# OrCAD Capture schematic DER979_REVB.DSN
size D
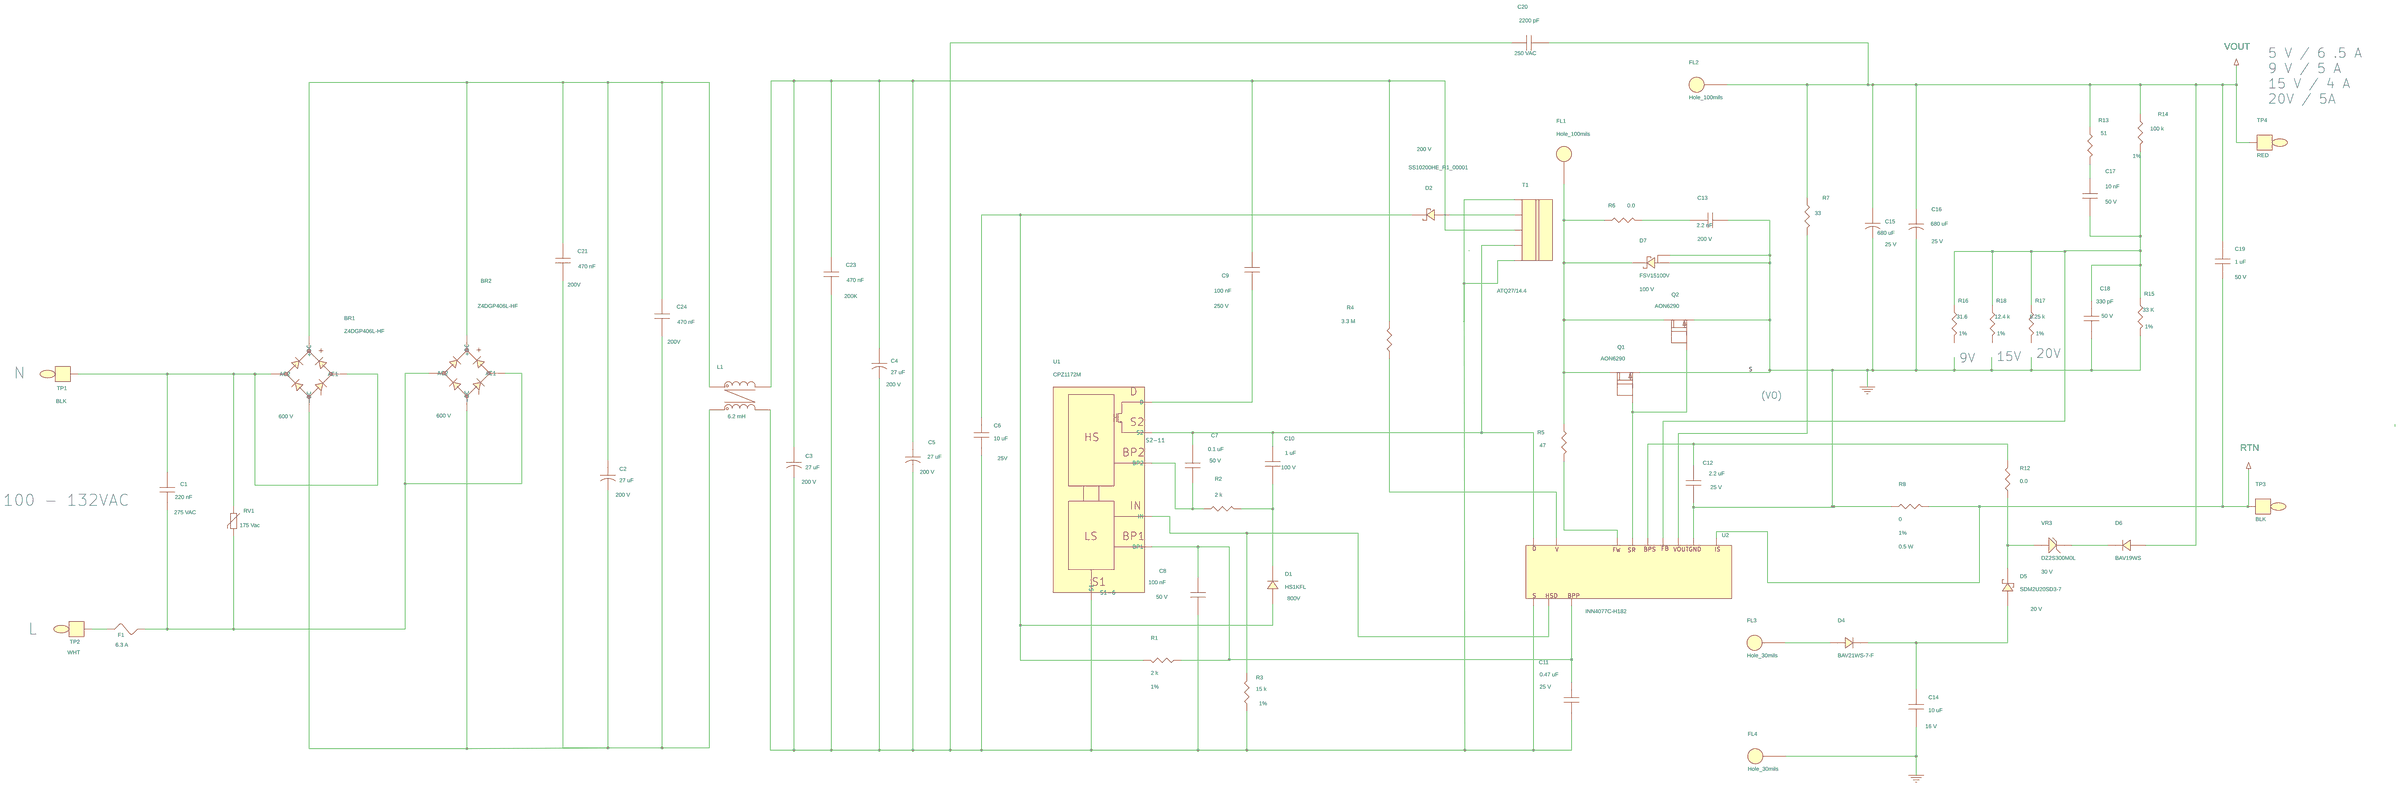
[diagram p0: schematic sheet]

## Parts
BR1  Z4DGP406L-HF  [pi_sm_d_z4d]
BR2  Z4DGP406L-HF  [pi_sm_d_z4d]
C1  220 nF  [pinpxcaprad475x255500040]
C2  27 uF  [pipolcapcyld400ls200040]
C3  27 uF  [pipolcapcyld400ls200040]
C4  27 uF  [pipolcapcyld400ls200040]
C5  27 uF  [pipolcapcyld400ls200040]
C6  10 uF  [pismc0805]
C7  0.1 uF  [pismc0603]
C8  100 nF  [pismc0603]
C9  100 nF  [pismc1206]
C10  1 uF  [pismc0805]
C11  0.47 uF  [pismc0805]
C12  2.2 uF  [pismc0805]
C13  2.2 nF  [pismc0805]
C14  10 uF  [pismc0805]
C15  680 uF  [pipolcapcyld8mmd030]
C16  680 uF  [pipolcapcyld8mmd030]
C17  10 nF  [pismr0402]
C18  330 pF  [pismc0603]
C19  1 uF  [pismc0805]
C20  2200 pF  [pinpcapraD9mmxLS10mm030]
C21  470 nF  [pismc1812]
C23  470 nF  [pismc1812]
C24  470 nF  [pismc1812]
D1  HS1KFL  [pi_sm_sod-123_12]
D2  SS10200HE_R1_00001  [pi_sm_sod-123HE]
D4  BAV21WS-7-F  [pismsod323]
D5  SDM2U20SD3-7  [pismsod323]
D6  BAV19WS  [pismsod323]
D7  FSV15100V  [pi_sm_d_to-277a]
F1  6.3 A  [pi_v_ax_3-6x10_145ls200d030]
FL1  Hole_100mils  [pi_hole_100mil]
FL2  Hole_100mils  [pi_hole_100mil]
FL3  Hole_30mils  [pi_hole_30mil]
FL4  Hole_30mils  [pi_hole_30mil]
L1  6.2 mH  [pi_CMC_18mH_Sumida]
Q1  AON6290  [pismpqfn5x6b]
Q2  AON6290  [pismpqfn5x6b]
R1  2 k  [pismr0603]
R2  2 k  [pismr0603]
R3  15 k  [pismr0603]
R4  3.3 M  [pismr1206]
R5  47  [pismr0603]
R6  0.0  [pismr1206]
R7  33  [pismr0603]
R8  0  [pismr0805]
R12  0.0  [pismr0603]
R13  51  [pismr0402]
R14  100 k  [pismr0603]
R15  33 K  [pismr0603]
R16  31.6  [pismr0603]
R17  8.25 k  [pismr0603]
R18  12.4 k  [pismr0603]
RV1  175 Vac  [pi_disc_335x240ls200d040]
T1  ATQ27/14.4  [pi_bobbin_ATQ27_V_5P]
TP1  BLK  [pitpkeystone100x100]
TP2  WHT  [pitpkeystone100x100]
TP3  BLK  [pitpkeystone100x100]
TP4  RED  [pitpkeystone100x100]
U1  CPZ1172M  [PI_SM_MinSOP16A_1]
U2  INN4077C-H182  [pi_ic_insop_24d_IPC]
VR3  DZ2S300M0L  [pi_sm_d_ssmini2p]

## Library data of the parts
BR1 BR2 = DISCRETE_BRIDGE_+~~-: Disp_Voltage: 600 V; Part Number: 15-01613-00
C1 = CAP_NP: COMPGROUP: 1; Disp_Voltage: 275 VAC; Part Number: 20-00776-00; Voltage: 275 VAC
C2-C5 = CAP_POL: ALT_SYMBOLS: pipolcapclyd400x675ls200040h; Disp_Voltage: 200 V; FPLIST: pipolcapcyld400ls200040,pipolcapclyd400x675ls200040h; Part Number: 20-00610-00; Voltage: 200 V
C6 = CAP_NP: Disp_Voltage: 25V; Part Number: 20-01673-00; Voltage: 25 V
C7 = CAP_NP: ALT_SYMBOLS: cc0603; Disp_Voltage: 50 V; FPLIST: pismc0603,cc0603; Part Number: 20-01434-00; ROOM: 2; Voltage: 50 V
C8 = CAP_NP: Disp_Voltage: 50 V; Part Number: 20-01693-00; ROOM: 2; Voltage: 50 V
C9 = CAP_NP: Disp_Voltage: 250 V; Part Number: 20-01011-00; ROOM: 1; Voltage: 250 V
C10 = CAP_NP: Disp_Voltage: 100 V; Part Number: 20-01324-00; ROOM: 2; Voltage: 100 V
C11 = CAP_NP: Disp_Voltage: 25 V; Part Number: 20-09182-00; ROOM: 3; Voltage: 25 V
C12 = CAP_NP: Disp_Voltage: 25 V; Part Number: 20-01594-00; ROOM: 3; Voltage: 25 V
C13 = CAP_NP: Disp_Voltage: 200 V; Part Number: 20-00761-00; ROOM: 3; Voltage: 200 V
C14 = CAP_NP: Disp_Voltage: 16 V; Part Number: 20-08964-00; ROOM: 3; Voltage: 16 V
C15 = CAP_POL: ALT_SYMBOLS: pipolcapcyld8x16mmd030H; COMPGROUP: 3; Disp_Voltage: 25 V; FPLIST: pipolcapcyld8mmd030,pipolcapcyld8x16mmd030H; Part Number: 20-01579-00; ROOM: 3; Voltage: 25 V
C16 = CAP_POL: ALT_SYMBOLS: pipolcapcyld8x16mmd030H; Disp_Voltage: 25 V; FPLIST: pipolcapcyld8mmd030,pipolcapcyld8x16mmd030H; Part Number: 20-01579-00; ROOM: 3; Voltage: 25 V
C17 = CAP_NP: Disp_Voltage: 50 V; Part Number: 20-09250-00; ROOM: 3; Voltage: 50 V
C18 = CAP_NP: ALT_SYMBOLS: pismc0603_1; Disp_Voltage: 50 V; FPLIST: pismc0603,pismc0603_1; Part Number: 20-09235-00; ROOM: 3; Voltage: 50 V
C19 = CAP_NP: Disp_Voltage: 50 V; Part Number: 20-00853-00; ROOM: 4; Voltage: 50 V
C20 = CAP_NP: Disp_Voltage: 250 VAC; Part Number: 20-01656-00; Voltage: 250 VAC
C21 C24 = CAP_NP: Disp_Voltage: 200V; Part Number: 20-08693-00; Voltage: 200V
C23 = CAP_NP: Disp_Voltage: 200K; Part Number: 20-08693-00; Voltage: 200V
D1 = DIODE: COMPGROUP: 2; Disp_Voltage: 800V; Part Number: 15-01686-00; ROOM: 2
D2 = DIODE_SCHOTTKY: Disp_Voltage: 200 V; Part Number: 15-01774-00; ROOM: 1
D4 = DIODE: Part Number: 15-00385-00
D5 = DIODE_SCHOTTKY: Disp_Voltage: 20 V; Part Number: 15-01176-00
D6 = DIODE: Part Number: 15-00658-00
D7 = DIODE_SCHOTTKY_TO-277A: Disp_Voltage: 100 V; Part Number: 15-01838-00
F1 = FUSE: ALT_SYMBOLS: pi_axial_3_6x10_145ls500d030; FPLIST: pi_v_ax_3-6x10_145ls200d030,pi_axial_3_6x10_145ls500d030; Part Number: 40-00028-00
FL1 = FlyingLead: Part Number: 35-00432-00
FL2 = FlyingLead: Part Number: 35-00432-00; ROOM: 3
FL3 FL4 = FlyingLead: Part Number: 35-00284-00; ROOM: 3
L1 = TORRID_4P_12_43a: ALT_SYMBOLS: pi_CMC_18mH_SumidaW,pi_CMC_18mH_Sumida_H,pi_CMC_18mH_SumidaSF; FPLIST: pi_CMC_18mH_Sumida,pi_CMC_18mH_SumidaW,pi_CMC_18mH_Sumida_H,pi_CMC_18mH_SumidaSF; Part Number: 30-00462-00
Q1 Q2 = FET_N_SGD_123_4_5678: Part Number: 50-00328-00; ROOM: 3
R1 = R: Disp_Tol: 1%; Part Number: 05-01107-00; ROOM: 2
R2 = R: ALT_SYMBOLS: pismr0603_1; FPLIST: pismr0603,pismr0603_1; Part Number: 05-01695-00; ROOM: 2
R3 = R: Disp_Tol: 1%; Part Number: 05-03199-00; ROOM: 2
R4 = R: Part Number: 05-01433-00; ROOM: 2
R5 = R: ALT_SYMBOLS: pismr0603_1; FPLIST: pismr0603,pismr0603_1; Part Number: 05-01656-00; ROOM: 4
R6 = R: Part Number: 05-03160-00; ROOM: 3
R7 = R: Part Number: 05-01652-00; ROOM: 3
R8 = R: Disp_Power: 0.5 W; Disp_Tol: 1%; Part Number: 05-06481-00
R12 = R: Part Number: 05-03158-00; ROOM: 3
R13 = R: Part Number: 05-06185-00; ROOM: 3
R14 = R: Disp_Tol: 1%; Part Number: 05-01174-00; ROOM: 3
R15 = R: Disp_Tol: 1%; Part Number: 05-06465-00; ROOM: 3
R16 = R: Disp_Tol: 1%; Part Number: 05-00934-00; ROOM: 3
R17 = R: Disp_Tol: 1%; Part Number: 05-01166-00; ROOM: 3
R18 = R: Disp_Tol: 1%; Part Number: 05-03191-00; ROOM: 3
RV1 = VARISTOR: Part Number: 85-00025-00
T1 = BATQ27_5P_GENERIC: Part Number: 25-01192-00
TP1 TP3 = TESTPOINT: ALT_SYMBOLS: TP_TH_CR2_D1_1; FPLIST: pitpkeystone100x100,TP_TH_CR2_D1_1; Part Number: 35-00079-00
TP2 = TESTPOINT: Part Number: 35-00081-00
TP4 = TESTPOINT: Part Number: 35-00080-00
U1 = ClampZeroMinSOP16: Part Number: 10-01212-00; ROOM: 2
U2 = MinnoPriSecCZ: ALT_SYMBOLS: pi_ic_insop_24d,PI_IC_INSOP24B; FPLIST: pi_ic_insop_24d_IPC, pi_ic_insop_24d,PI_IC_INSOP24B; Part Number: 10-01408-00; ROOM: 3
VR3 = DIODE_ZENER: Disp_Voltage: 30 V; Part Number: 15-00996-00

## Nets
GND: C12.2 C13.1 C14.2 C15.2 C16.2 C18.2 D7.1(A1) D7.2(A2) FL4.1 Q1.1(S) Q2.1(S) R8.2 R15.2 U2.2
RTN: C19.1 R8.1 TP3.1 U2.1
Vout: C15.1 C16.1 C19.2 C20.2 D6.2 FL2.1 R7.1 R13.1 R14.1 TP4.1
N10971121: C8.1 C11.1 R1.2 U1.8(BP1) U2.14
N10972629: C17.2 C18.1 R14.2 R15.1 R16.1 R17.1 R18.1 U2.3
N10986441: R4.2 U2.13
N10993526: C7.2 C10.1 T1.4 U1.10(S2) U2.24
N11033773: C3.2 C4.2 C5.2 C6.2 C8.2 C11.2 C20.1 C23.2 L1.2 R3.1 T1.1 T1.5 U1.3(S1) U2.16
N11038315: C3.1 C4.1 C5.1 C9.1 C23.1 L1.3 R4.1 T1.3
N11038383: C9.2 U1.16(D)
N11093530: D7.3(Cathode) FL1.1 Q1.5(D) Q2.5(D) R5.1 R6.2
N11118683: R3.2 U1.7(IN) U2.15
N11129317: R5.2 U2.7
N11134278: Q1.4(G) Q2.4(G) U2.5
N11138918: C17.1 R13.2
N11256131: C7.1 R2.1 U1.9(BP2)
N11484512: R7.2 U2.6
N11515908: C10.2 D1.1 R2.2
N12555875: C12.1 R12.2 U2.4
N13144639: C13.2 R6.1
N13180601: C14.1 D4.1 D5.2
N13197624: D4.2 FL3.1
N13230820: D2.2 T1.2
N13361044: C6.1 D1.2 D2.1 R1.1
N13388475: BR1.1(+DC) BR2.1(+DC) C2.1 C21.1 C24.1 L1.4
N13388575: BR1.2(AC1) BR1.3(AC2) C1.1 RV1.1 TP1.1
N13388715: BR1.4(-DC) BR2.4(-DC) C2.2 C21.2 C24.2 L1.1
N13388781: BR2.2(AC1) BR2.3(AC2) C1.2 F1.2 RV1.2
N13388817: F1.1 TP2.1
N13395881: D5.1 R12.1 VR3.2
N13397632: D6.1 VR3.1

Not connected (* = marked no-connect by the designer): Q1 2(S2) 3(S3) 6(D6) 7(D7) 8(D8); Q2 2(S2) 3(S3) 6(D6) 7(D7) 8(D8); R16 2; R17 2; R18 2; U1 6(S1-6) 11(S2-11)

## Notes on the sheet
- 5 V / 6 .5 A
  9 V / 5 A
  15 V / 4 A
  20V / 5A
- 15V
- 20V
- 9V
- N
- (VO)
- 100 - 132VAC
- L
